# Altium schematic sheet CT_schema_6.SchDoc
size 226 x 144 mm
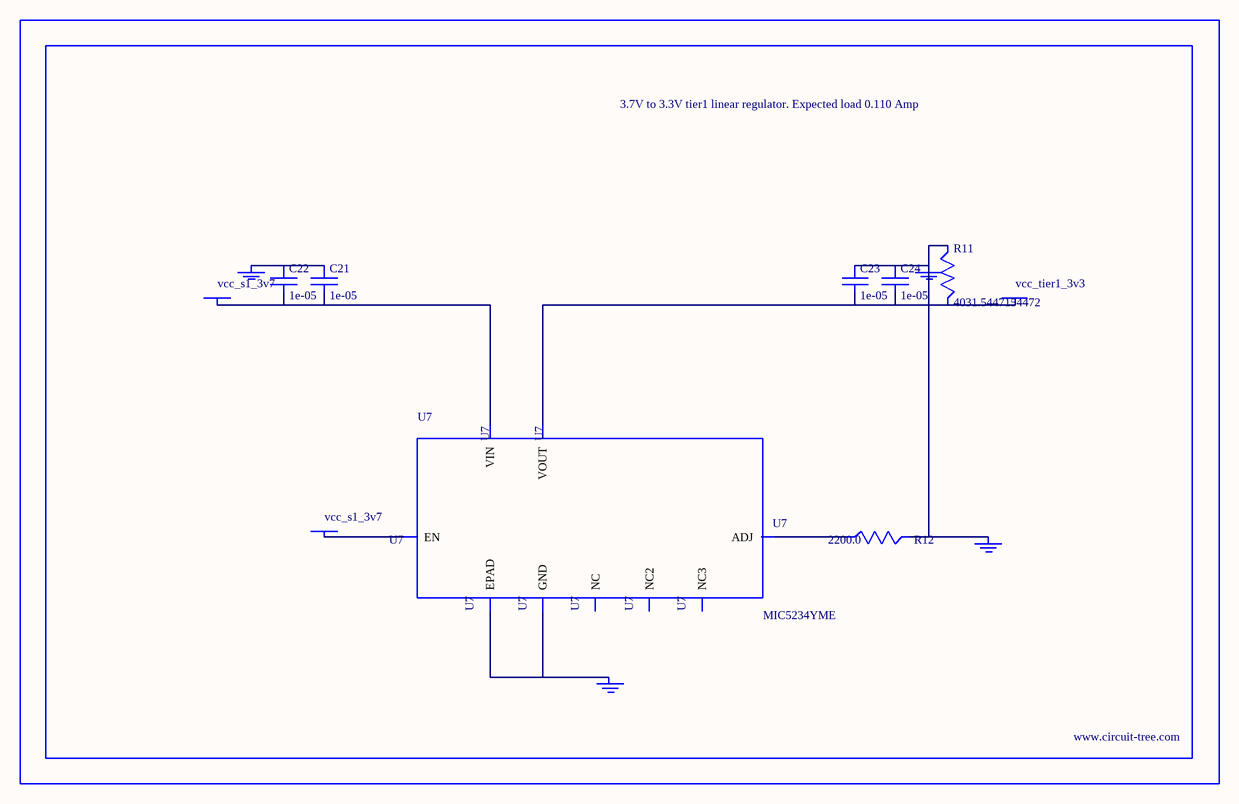
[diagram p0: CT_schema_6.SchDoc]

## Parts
BORDER5  (no value)
C21  1e-05  [C1210]
C22  1e-05  [C1210]
C23  1e-05  [C1210]
C24  1e-05  [C1210]
GND_INSTANCE_5_0  (no value)
GND_INSTANCE_5_1  (no value)
GND_INSTANCE_5_2  (no value)
GND_INSTANCE_5_3  (no value)
POWER_INSTANCE_5_0  vcc_tier1_3v3
POWER_INSTANCE_5_1  vcc_s1_3v7
POWER_INSTANCE_5_2  vcc_s1_3v7
R11  4031.5447154472  [R0603]
R12  2200.0  [R0603]
U7  MIC5234YME  [SOIC-8_EP]

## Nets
NetC21_1: C21.1 C22.1 GND_INSTANCE_5_3.0(GND)
NetC21_2: C21.2 C22.2 POWER_INSTANCE_5_2.0(PWR) U7.8(VIN)
NetC23_1: C23.1 C24.1 GND_INSTANCE_5_0.0(GND) GND_INSTANCE_5_1.0(GND) R11.1 R12.2
NetC23_2: C23.2 C24.2 POWER_INSTANCE_5_0.0(PWR) R11.2 U7.1(VOUT)
NetGND_INSTANCE_5_2_0: GND_INSTANCE_5_2.0(GND) U7.7(GND) U7.EPAD
NetPOWER_INSTANCE_5_1_0: POWER_INSTANCE_5_1.0(PWR) U7.5(EN)
NetR12_1: R12.1 U7.4(ADJ)

Not connected (* = marked no-connect by the designer): U7 2(NC) 3(NC2) 6(NC3)

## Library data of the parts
BORDER5 = BORDER_PAGE5
C21-C24 = C1210C106K5PACTU
GND_INSTANCE_5_0-GND_INSTANCE_5_3 = GND
POWER_INSTANCE_5_0-POWER_INSTANCE_5_2 = PWR
R11 = R11
R12 = RC0603JR-072K2L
